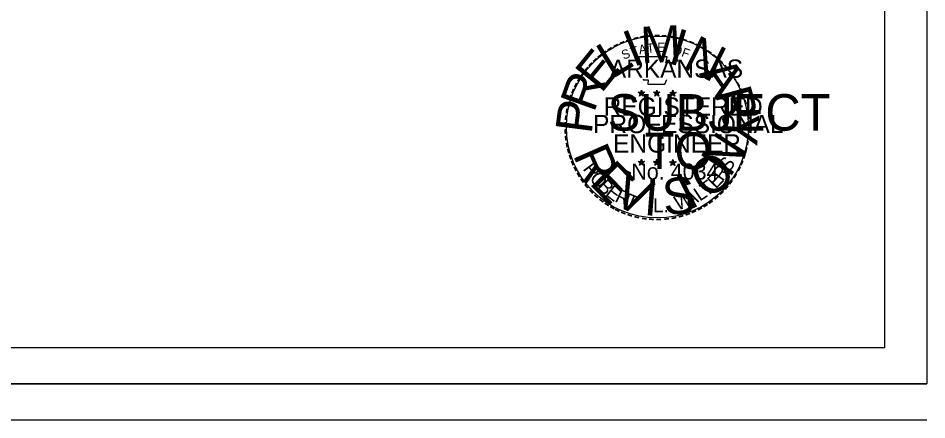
# Model space of a CAD drawing. Extents: x 23481 to 28196, y 1325020 to 1327623.
# Drawn here: x 26099 to 27092, y 1325370 to 1325809 of the extents above; entities that cross this region are included whole.
import ezdxf

# ---------------------------------------------------------------- set-up
doc = ezdxf.new("R2010")
doc.units = 0
for name, color, linetype in [('S_ELECTRIC_UTILITIES_ANNOT', 7, 'Continuous'), ('S_PRIMARY_CTL_ANNOT', 7, 'Continuous'), ('S_STREAM', 7, 'Continuous')]:
    doc.layers.add(name, color=color, linetype=linetype)

msp = doc.modelspace()

# ---------------------------------------------------------------- linework, layer by layer
at = {"layer": 'S_ELECTRIC_UTILITIES_ANNOT'}
for p, q in [((27045.67, 1325448.4), (27045.67, 1327502.83)), ((27045.67, 1325448.4), (23883.86, 1325448.4)), ((23818.18, 1325408.97), (27091.73, 1325408.97)), ((23818.18, 1325369.6), (27091.73, 1325369.6))]:
    msp.add_line(p, q, dxfattribs=at)
msp.add_circle((26797.19, 1325689.76), 99.45, dxfattribs=at)
at = {"layer": 'S_PRIMARY_CTL_ANNOT'}
msp.add_lwpolyline([(23808.34, 1327542.3), (27091.73, 1327542.3), (27091.73, 1325408.97), (23808.34, 1325408.97)], close=True, dxfattribs=at)
at = {"layer": 'S_STREAM'}
for p, q in [((26776.32, 1325727.7), (26779.81, 1325726.59)), ((26776.32, 1325727.7), (26778.85, 1325727.25)), ((26776.32, 1325727.7), (26778.69, 1325726.48)), ((26777.65, 1325723.62), (26779.81, 1325726.59)), ((26777.65, 1325723.62), (26778.91, 1325726.06)), ((26777.65, 1325723.62), (26779.79, 1325725.79)), ((26779.81, 1325730.24), (26779.4, 1325727.72)), ((26781.94, 1325723.62), (26779.79, 1325725.76)), ((26779.81, 1325726.59), (26779.81, 1325730.24)), ((26779.81, 1325730.24), (26780.3, 1325727.74)), ((26783.28, 1325727.7), (26779.81, 1325726.59)), ((26781.94, 1325723.62), (26779.81, 1325726.59)), ((26783.28, 1325727.7), (26780.42, 1325727.21)), ((26781.94, 1325723.62), (26780.57, 1325726.53)), ((26783.28, 1325727.7), (26781.24, 1325726.68)), ((26793.02, 1325727.7), (26796.51, 1325726.59)), ((26793.02, 1325727.7), (26795.55, 1325727.25)), ((26793.02, 1325727.7), (26795.39, 1325726.48)), ((26794.35, 1325723.62), (26796.51, 1325726.59)), ((26794.35, 1325723.62), (26795.61, 1325726.06)), ((26794.35, 1325723.62), (26796.49, 1325725.79)), ((26796.51, 1325730.24), (26796.1, 1325727.72)), ((26798.64, 1325723.62), (26796.49, 1325725.76)), ((26796.51, 1325726.59), (26796.51, 1325730.24)), ((26796.51, 1325730.24), (26797, 1325727.74)), ((26799.98, 1325727.7), (26796.51, 1325726.59)), ((26798.64, 1325723.62), (26796.51, 1325726.59)), ((26799.98, 1325727.7), (26797.12, 1325727.21)), ((26798.64, 1325723.62), (26797.27, 1325726.53)), ((26799.98, 1325727.7), (26797.94, 1325726.68)), ((26810.66, 1325727.58), (26814.15, 1325726.47)), ((26810.66, 1325727.58), (26813.19, 1325727.13)), ((26810.66, 1325727.58), (26813.03, 1325726.36)), ((26811.99, 1325723.5), (26814.15, 1325726.47)), ((26811.99, 1325723.5), (26813.25, 1325725.94)), ((26811.99, 1325723.5), (26814.13, 1325725.67)), ((26814.15, 1325730.12), (26813.74, 1325727.6)), ((26816.28, 1325723.5), (26814.13, 1325725.64)), ((26814.15, 1325726.47), (26814.15, 1325730.12)), ((26814.15, 1325730.12), (26814.64, 1325727.62)), ((26817.62, 1325727.58), (26814.15, 1325726.47)), ((26816.28, 1325723.5), (26814.15, 1325726.47)), ((26817.62, 1325727.58), (26814.76, 1325727.09)), ((26816.28, 1325723.5), (26814.91, 1325726.41)), ((26817.62, 1325727.58), (26815.58, 1325726.56)), ((26776.28, 1325651.97), (26779.77, 1325650.86)), ((26776.28, 1325651.97), (26778.81, 1325651.52)), ((26776.28, 1325651.97), (26778.65, 1325650.75)), ((26779.77, 1325654.51), (26779.36, 1325651.99)), ((26779.77, 1325650.86), (26779.77, 1325654.51)), ((26779.77, 1325654.51), (26780.26, 1325652.01)), ((26783.24, 1325651.97), (26779.77, 1325650.86)), ((26783.24, 1325651.97), (26780.38, 1325651.48)), ((26783.24, 1325651.97), (26781.2, 1325650.95)), ((26792.97, 1325651.97), (26796.46, 1325650.86)), ((26792.97, 1325651.97), (26795.5, 1325651.52)), ((26792.97, 1325651.97), (26795.34, 1325650.75)), ((26796.46, 1325654.51), (26796.05, 1325651.99)), ((26796.46, 1325650.86), (26796.46, 1325654.51)), ((26796.46, 1325654.51), (26796.95, 1325652.01)), ((26799.93, 1325651.97), (26796.46, 1325650.86)), ((26799.93, 1325651.97), (26797.07, 1325651.48)), ((26799.93, 1325651.97), (26797.89, 1325650.95)), ((26810.64, 1325651.87), (26814.13, 1325650.76)), ((26810.64, 1325651.87), (26813.17, 1325651.42)), ((26810.64, 1325651.87), (26813.01, 1325650.65)), ((26814.13, 1325654.41), (26813.72, 1325651.89)), ((26814.13, 1325650.76), (26814.13, 1325654.41)), ((26814.13, 1325654.41), (26814.62, 1325651.91)), ((26817.6, 1325651.87), (26814.13, 1325650.76)), ((26817.6, 1325651.87), (26814.74, 1325651.38)), ((26817.6, 1325651.87), (26815.56, 1325650.85)), ((26777.61, 1325647.89), (26779.77, 1325650.86)), ((26777.61, 1325647.89), (26778.87, 1325650.33)), ((26777.61, 1325647.89), (26779.75, 1325650.06)), ((26781.9, 1325647.89), (26779.75, 1325650.03)), ((26781.9, 1325647.89), (26779.77, 1325650.86)), ((26781.9, 1325647.89), (26780.53, 1325650.8)), ((26794.3, 1325647.89), (26796.46, 1325650.86)), ((26794.3, 1325647.89), (26795.56, 1325650.33)), ((26794.3, 1325647.89), (26796.44, 1325650.06)), ((26798.59, 1325647.89), (26796.44, 1325650.03)), ((26798.59, 1325647.89), (26796.46, 1325650.86)), ((26798.59, 1325647.89), (26797.22, 1325650.8)), ((26811.97, 1325647.79), (26814.13, 1325650.76)), ((26811.97, 1325647.79), (26813.23, 1325650.23)), ((26811.97, 1325647.79), (26814.11, 1325649.96)), ((26816.26, 1325647.79), (26814.11, 1325649.93)), ((26816.26, 1325647.79), (26814.13, 1325650.76)), ((26816.26, 1325647.79), (26814.89, 1325650.7))]:
    msp.add_line(p, q, dxfattribs=at)
for points in [[(26776.73, 1325766.48), (26779.42, 1325758.21)], [(26811.84, 1325757.26), (26813.26, 1325760.1), (26806.41, 1325759.86), (26807.89, 1325766.48), (26776.73, 1325766.48)], [(26781.65, 1325742.25), (26781.65, 1325741.38), (26787.28, 1325741.19), (26786.74, 1325736.46), (26805.44, 1325736.46), (26807.45, 1325741.82)], [(26779.81, 1325730.24), (26781.94, 1325723.62), (26776.32, 1325727.7), (26783.28, 1325727.7), (26777.65, 1325723.62), (26779.81, 1325730.24)], [(26796.51, 1325730.24), (26798.64, 1325723.62), (26793.02, 1325727.7), (26799.98, 1325727.7), (26794.35, 1325723.62), (26796.51, 1325730.24)], [(26814.15, 1325730.12), (26816.28, 1325723.5), (26810.66, 1325727.58), (26817.62, 1325727.58), (26811.99, 1325723.5), (26814.15, 1325730.12)], [(26779.77, 1325654.51), (26781.9, 1325647.89), (26776.28, 1325651.97), (26783.24, 1325651.97), (26777.61, 1325647.89), (26779.77, 1325654.51)], [(26796.46, 1325654.51), (26798.59, 1325647.89), (26792.97, 1325651.97), (26799.93, 1325651.97), (26794.3, 1325647.89), (26796.46, 1325654.51)], [(26814.13, 1325654.41), (26816.26, 1325647.79), (26810.64, 1325651.87), (26817.6, 1325651.87), (26811.97, 1325647.79), (26814.13, 1325654.41)]]:
    msp.add_lwpolyline(points, dxfattribs=at)
for centre, radius in [((26779.8, 1325726.58), 1.72), ((26779.8, 1325726.58), 1.45), ((26779.8, 1325726.58), 1.16), ((26779.8, 1325726.58), 0.991), ((26779.8, 1325726.58), 0.747), ((26779.8, 1325726.58), 0.495), ((26779.8, 1325726.58), 0.296), ((26796.5, 1325726.58), 1.72), ((26796.5, 1325726.58), 1.45), ((26796.5, 1325726.58), 1.16), ((26796.5, 1325726.58), 0.991), ((26796.5, 1325726.58), 0.747), ((26796.5, 1325726.58), 0.495), ((26796.5, 1325726.58), 0.296), ((26814.14, 1325726.46), 1.72), ((26814.14, 1325726.46), 1.45), ((26814.14, 1325726.46), 1.16), ((26814.14, 1325726.46), 0.991), ((26814.14, 1325726.46), 0.747), ((26814.14, 1325726.46), 0.495), ((26814.14, 1325726.46), 0.296), ((26779.76, 1325650.85), 1.72), ((26779.76, 1325650.85), 1.45), ((26779.76, 1325650.85), 1.16), ((26779.76, 1325650.85), 0.991), ((26779.76, 1325650.85), 0.747), ((26779.76, 1325650.85), 0.495), ((26779.76, 1325650.85), 0.296), ((26796.45, 1325650.85), 1.72), ((26796.45, 1325650.85), 1.45), ((26796.45, 1325650.85), 1.16), ((26796.45, 1325650.85), 0.991), ((26796.45, 1325650.85), 0.747), ((26796.45, 1325650.85), 0.495), ((26796.45, 1325650.85), 0.296), ((26814.12, 1325650.75), 1.72), ((26814.12, 1325650.75), 1.45), ((26814.12, 1325650.75), 1.16), ((26814.12, 1325650.75), 0.991), ((26814.12, 1325650.75), 0.747), ((26814.12, 1325650.75), 0.495), ((26814.12, 1325650.75), 0.296)]:
    msp.add_circle(centre, radius, dxfattribs=at)

# ---------------------------------------------------------------- texts
at = {"layer": 'S_ELECTRIC_UTILITIES_ANNOT'}
for s, rotation, p in [('M', 2.69429, (26779.58, 1325759.29)), ('I', 22.01053, (26770.86, 1325754.92)), ('I', 343.37806, (26807.76, 1325759.95)), ('L', 31.66865, (26747.67, 1325741.79)), ('N', 333.71994, (26823.54, 1325755.13)), ('E', 50.98488, (26735.85, 1325725.69)), ('A', 304.74559, (26842.29, 1325748.05)), ('R', 70.30112, (26727.85, 1325704.6)), ('R', 285.42935, (26859.6, 1325727.82)), ('P', 82.60888, (26725.23, 1325681.32)), ('Y', 266.11312, (26868.76, 1325706.33)), ('N', 57.13775, (26876.29, 1325633.36)), ('R', 293.76387, (26704.46, 1325659.53)), ('E', 314.32618, (26721.69, 1325628.17)), ('O', 36.57544, (26852, 1325609.58)), ('V', 334.8885, (26746.47, 1325606.35)), ('I', 355.45081, (26781.69, 1325593.64)), ('S', 5.73197, (26804.85, 1325592.99)), ('I', 26.29428, (26831.62, 1325598.53))]:
    msp.add_text(s, height=40, rotation=rotation, dxfattribs=at).set_placement(p)
for s, p in [('SUBJECT', (26742.82, 1325685.74)), ('TO', (26783.21, 1325643.75))]:
    msp.add_text(s, height=39.999, dxfattribs=at).set_placement(p)
at = {"layer": 'S_STREAM'}
for s, height, rotation, p in [('-', 16, 5.89682, (26785.78, 1325782.87)), ('-', 16, 0.18623, (26793.5, 1325783.59)), ('-', 16, 357.74304, (26800.73, 1325783.46)), ('-', 16, 28.79182, (26751.54, 1325771.88)), ('-', 16, 24.30721, (26757.87, 1325775.05)), ('-', 16, 19.17608, (26764.21, 1325777.74)), ('-', 16, 13.63015, (26771.71, 1325780.15)), ('-', 16, 10.21935, (26778.49, 1325781.77)), ('T', 10, 6.02276, (26786.17, 1325770.73)), ('E', 10, 0.83234, (26797.22, 1325771.83)), ('-', 16, 352.16172, (26808.17, 1325782.9)), ('-', 16, 347.20489, (26815.36, 1325781.76)), ('-', 16, 342.3362, (26821.71, 1325780.21)), ('-', 16, 337.85509, (26829.06, 1325777.98)), ('-', 16, 334.12109, (26835.37, 1325775.27)), ('-', 16, 36.23174, (26739.79, 1325764.23)), ('-', 16, 34.06357, (26745.57, 1325768.18)), ('S', 10, 21.59401, (26760.28, 1325763.25)), ('T', 10, 16.4036, (26769.42, 1325766.56)), ('A', 10, 11.21318, (26777.68, 1325769.07)), ('O', 10, 350.4515, (26813.26, 1325769.73)), ('F', 10, 340.07066, (26822.8, 1325767.45)), ('-', 16, 329.64089, (26841.16, 1325772.44)), ('-', 16, 325.86266, (26847.59, 1325768.83)), ('-', 16, 48.42305, (26726.22, 1325751.5)), ('-', 16, 42.96224, (26730.7, 1325756.28)), ('-', 16, 38.95066, (26735.03, 1325760.45)), ('-', 16, 320.52971, (26853.69, 1325764.57)), ('-', 16, 315.57859, (26859.68, 1325759.69)), ('-', 16, 50.61418, (26722.19, 1325746.64)), ('-', 16, 309.87973, (26865.37, 1325754.19)), ('-', 16, 306.65218, (26870.62, 1325748.17)), ('-', 16, 58.07063, (26714.81, 1325735.7)), ('-', 16, 54.23247, (26718.06, 1325740.97)), ('-', 14, 303.67529, (26875.48, 1325742.49)), ('-', 16, 67.77427, (26709.09, 1325723.45)), ('-', 16, 62.87135, (26711.68, 1325729.56)), ('-', 16, 299.66835, (26878.67, 1325736.42)), ('-', 16, 294.66279, (26881.91, 1325730.3)), ('-', 16, 72.39447, (26706.9, 1325717.15)), ('-', 16, 290.57283, (26884.48, 1325724.53)), ('-', 16, 75.46096, (26704.93, 1325710.01)), ('-', 16, 285.12326, (26886.82, 1325718.73)), ('-', 16, 280.54934, (26888.82, 1325711.31)), ('-', 16, 85.18634, (26702.85, 1325695.97)), ('-', 16, 81.20126, (26703.61, 1325702.88)), ('-', 16, 276.59616, (26890.44, 1325703.63)), ('-', 16, 89.06224, (26702.6, 1325688.96)), ('-', 16, 274.33011, (26891.04, 1325696.41)), ('-', 16, 94.19588, (26702.95, 1325681.71)), ('-', 16, 263.5172, (26891.19, 1325683.43)), ('-', 16, 269.94067, (26891.38, 1325690.09)), ('-', 16, 98.94793, (26703.67, 1325675.04)), ('-', 16, 101.71495, (26705.02, 1325667.71)), ('-', 16, 260.99529, (26890.48, 1325676.89)), ('-', 16, 105.45785, (26706.64, 1325661.76)), ('-', 16, 255.7626, (26889.38, 1325670.11)), ('-', 16, 109.08742, (26708.79, 1325655.45)), ('-', 16, 114.06432, (26711.33, 1325649.49)), ('R', 15.4, 306.65526, (26715.06, 1325643.88)), ('S', 15.4, 55.05496, (26875.33, 1325639.1)), ('-', 16, 247.88866, (26885.34, 1325656.18)), ('-', 16, 252.86809, (26887.57, 1325662.91)), ('-', 16, 115.72885, (26714.38, 1325643.31)), ('R', 15.4, 55.48552, (26868.63, 1325629.53)), ('-', 16, 244.61971, (26882.72, 1325649.89)), ('-', 16, 120.44712, (26717.95, 1325637.45)), ('-', 16, 125.89344, (26721.98, 1325631.84)), ('O', 15.4, 311.26889, (26722.19, 1325633.07)), ('B', 15.4, 312.5498, (26730.6, 1325624.07)), ('T', 15.4, 36.10969, (26850.78, 1325613)), ('E', 15.4, 46.22597, (26861.11, 1325621.38)), ('-', 16, 233.84524, (26874.76, 1325635.84)), ('-', 16, 239.07125, (26878.78, 1325642.37)), ('-', 16, 130.71812, (26726.6, 1325626.32)), ('-', 16, 134.22381, (26731.77, 1325620.87)), ('E', 15.4, 322.50013, (26739.44, 1325615.68)), ('R', 15.4, 334.64611, (26749.75, 1325608.75)), ('L', 15.4, 33.43256, (26843.49, 1325608.03)), ('-', 16, 231.25377, (26870.46, 1325630.18)), ('-', 16, 138.93382, (26737.02, 1325616.23)), ('-', 16, 144.64634, (26742.58, 1325612.17)), ('T', 15.4, 337.48462, (26760.55, 1325603.37)), ('L.', 15.4, 0.51074, (26792.54, 1325596.5)), ('W', 15.4, 17.89908, (26818.85, 1325598.41)), ('A', 15.4, 24.24549, (26830.75, 1325602.53)), ('-', 16, 221.08509, (26860.45, 1325619.45)), ('-', 16, 225.76533, (26865.67, 1325624.54)), ('-', 16, 148.08978, (26748.19, 1325608.46)), ('-', 16, 151.57039, (26753.98, 1325605.21)), ('-', 16, 207.35684, (26844.04, 1325607.4)), ('-', 16, 212.24909, (26849.62, 1325610.86)), ('-', 16, 215.73633, (26854.96, 1325614.73)), ('-', 16, 154.60019, (26759.2, 1325602.74)), ('-', 16, 158.56121, (26765.44, 1325600.2)), ('-', 16, 162.79826, (26772.31, 1325598.07)), ('-', 16, 167.55551, (26779.46, 1325596.43)), ('-', 16, 191.28576, (26817.55, 1325597.07)), ('-', 16, 195.47429, (26824.84, 1325599.06)), ('-', 16, 200.71842, (26831.61, 1325601.48)), ('-', 16, 204.25161, (26837.8, 1325604.21)), ('-', 16, 173.11546, (26787.18, 1325595.33)), ('-', 16, 176.51827, (26794.66, 1325594.8)), ('-', 16, 181.59176, (26802.1, 1325594.99)), ('-', 16, 185.81666, (26810.19, 1325595.75))]:
    msp.add_text(s, height=height, rotation=rotation, dxfattribs=at).set_placement(p)
for s, height, p in [('ARKANSAS', 20, (26745.26, 1325743.59)), ('REGISTERED', 20, (26738.48, 1325702.1)), ('PROFESSIONAL', 20, (26727, 1325683.06)), ('ENGINEER', 20, (26748.87, 1325661.81)), ('No. 4034', 17.57, (26768.68, 1325632.3))]:
    msp.add_text(s, height=height, dxfattribs=at).set_placement(p)

doc.saveas('drawing.dxf')
